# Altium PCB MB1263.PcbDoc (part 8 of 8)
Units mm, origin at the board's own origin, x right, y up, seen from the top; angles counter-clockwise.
Board outline 86 x 120 mm, 6 copper layers (Top Layer, Signal Layer 1, Signal Layer 2, Signal Layer 3, Signal Layer 4, Bottom Layer), stack 1.556 mm thick; 392 components, 421 nets, 1978 pads, 1444 vias.
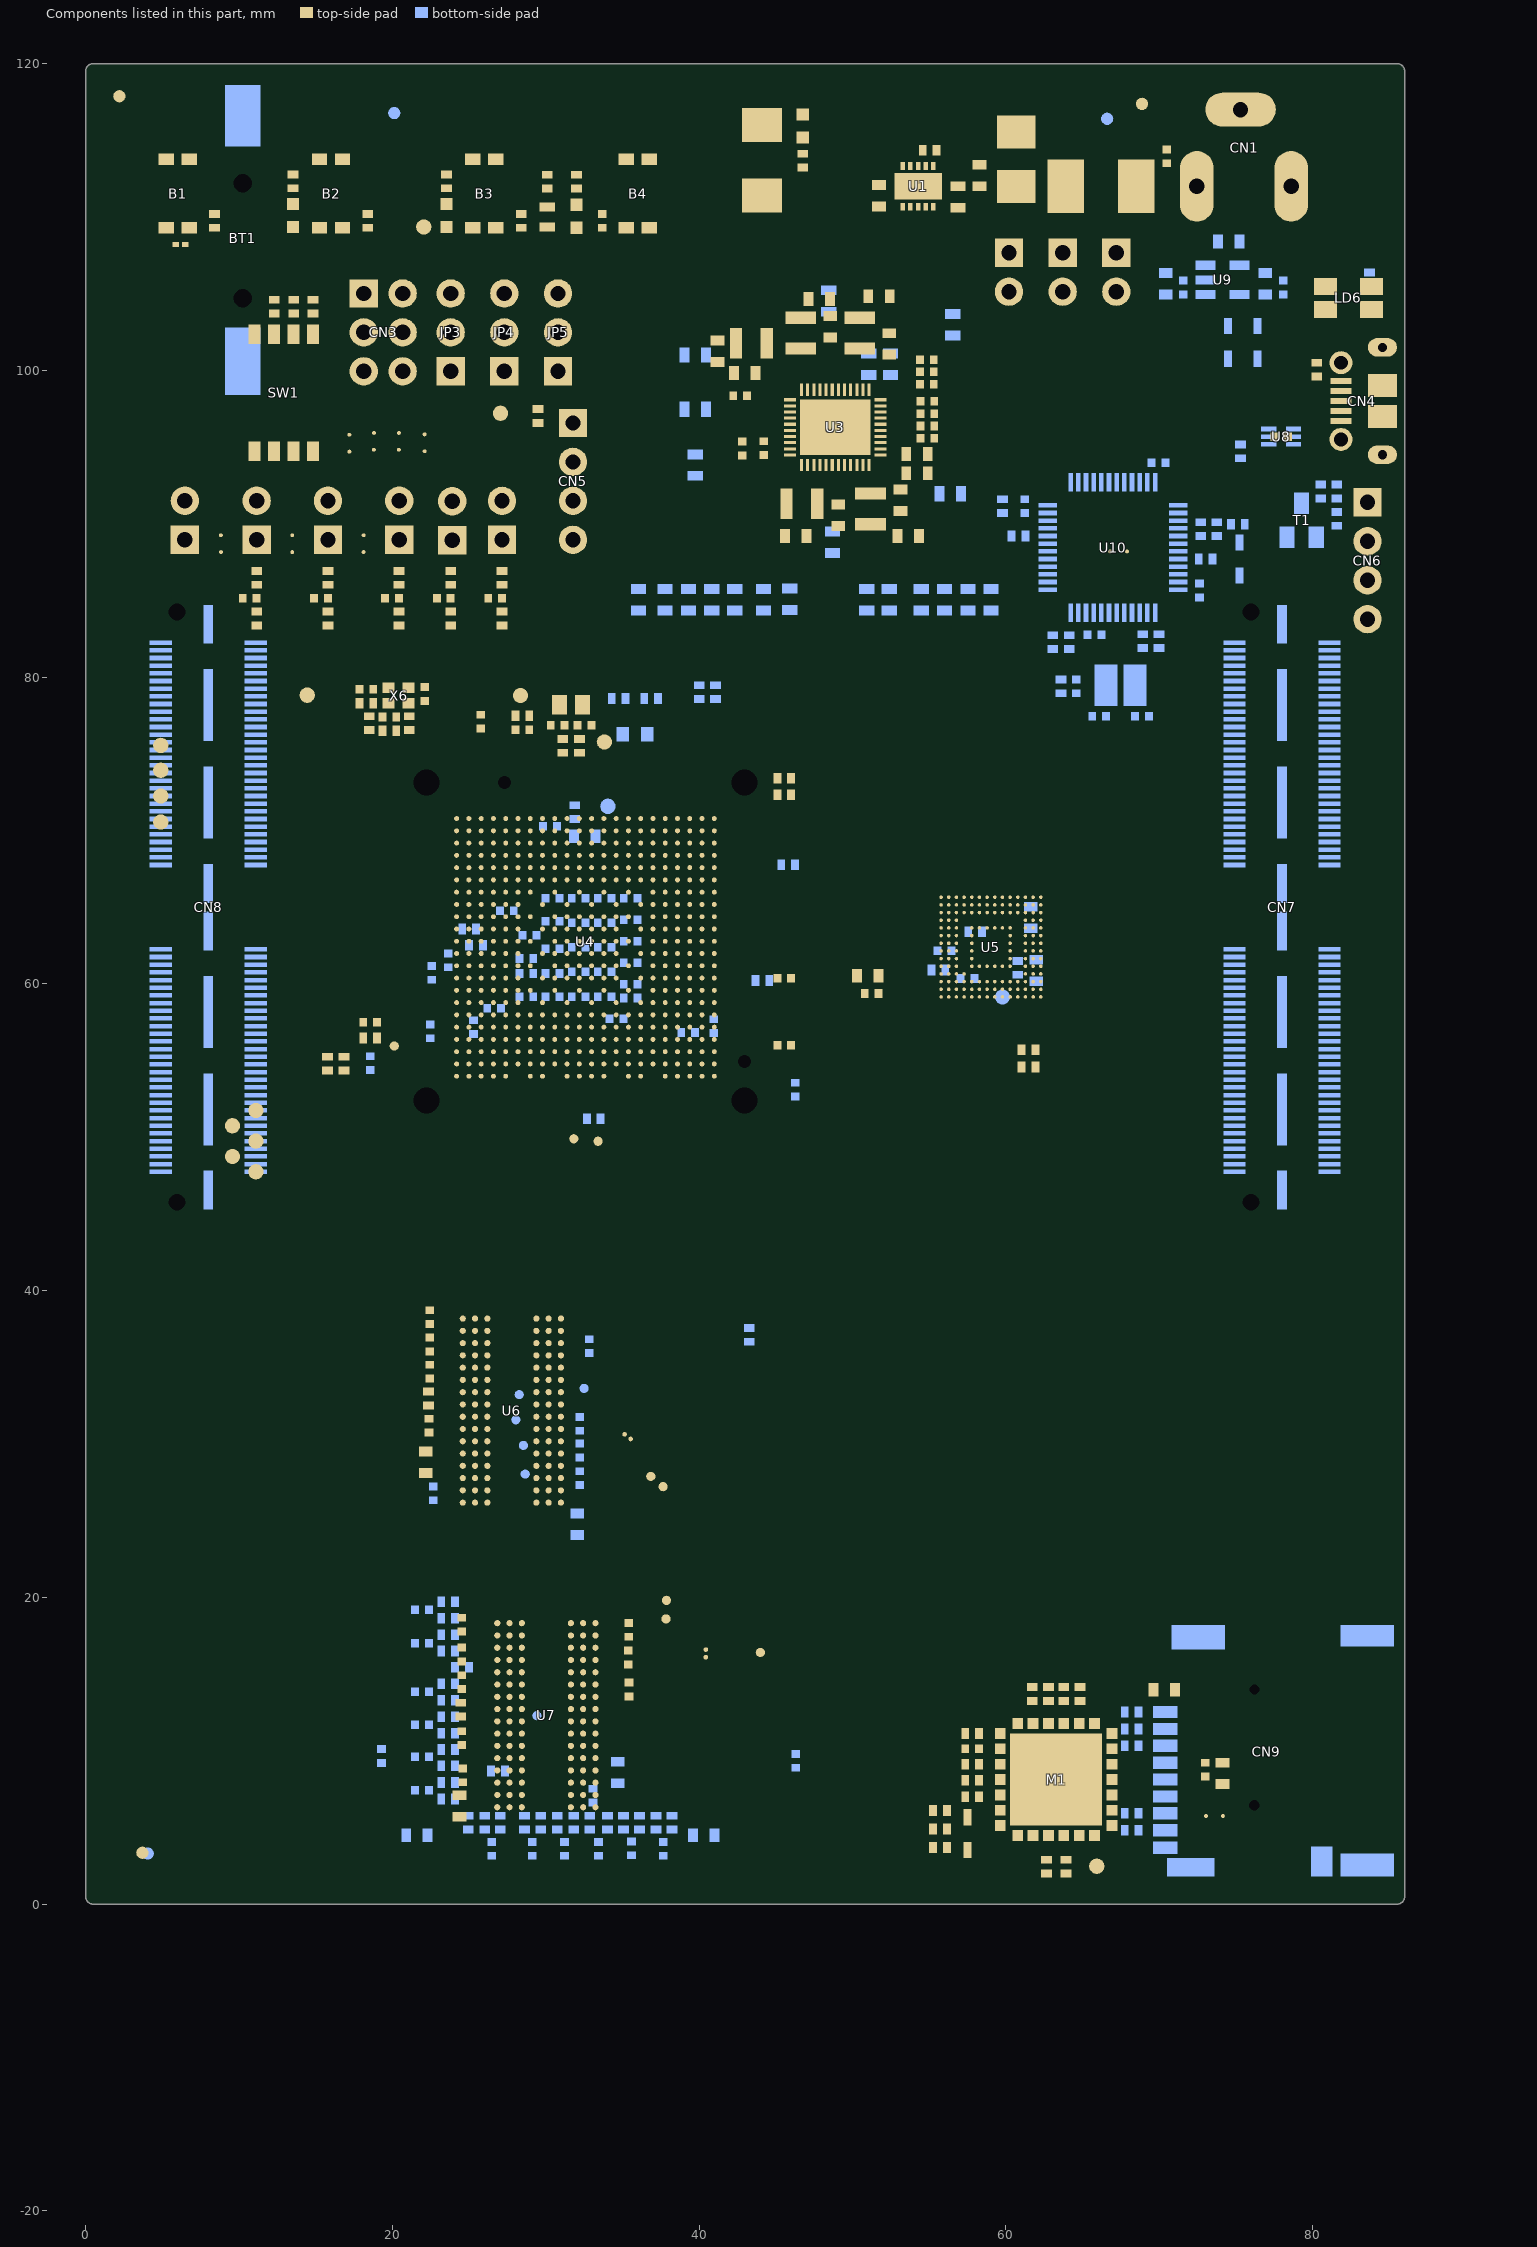
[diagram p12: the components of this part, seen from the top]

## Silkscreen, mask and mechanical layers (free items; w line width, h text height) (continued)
Drill Drawing:
  drawing of 518 lines, arcs and shapes, not listed
  text "IMPEDANCE TABLE" at -1,147.5 h3
  text "PCB SPECIFICATIONS :" at 94.25,146.25 h3
  text "LAYER" at 3.25,142.5 h3
  text "TRACE" at 19.5,142.5 h3
  text "SPACING" at 30,142.5 h3
  text "IMPEDANCE" at 43.5,142.5 h3
  text "IMPEDANCE" at 60.5,142.5 h3
  text "TOL." at 79.25,142.5 h3
  text "A.   MATERIAL :" at 94.25,142.25 h3
  text "FR-4" at 132.75,142.25 h3
  text "TG-170" at 149.25,142.25 h3
  text "X  TG-150" at 167.5,142.25 h3
  text "TG-140" at 183.5,142.25 h3
  text "(Single ended)" at 44,139.75 h2.5
  text "(Differentiel)" at 61.75,139.75 h2.5
  text "B.   MATERIAL FAMILY :" at 94.25,139.25 h3
  text "N/A" at 132.75,139.25 h3
  text "C.   SOLDERMASK COLOR :" at 94.25,136.25 h3
  text "GREEN" at 132.75,136.25 h3
  text "X  BLUE" at 149.25,136.25 h3
  text "RED" at 167.5,136.25 h3
  text "BLACK" at 183.5,136.25 h3
  text "TOP / BOTTOM" at -1,136 h3
  text "5.118" at 20.5,136 h3
  text "NA" at 32.5,136 h3
  text "50 ohm" at 47.25,136 h3
  text "NA" at 63.75,136 h3
  text "+/- 10%" at 77.75,136 h3
  text "D.   SILKSCREEN COLOR :" at 94.25,133.25 h3
  text "X  WHITE" at 132.75,133.25 h3
  text "YELLOW" at 149.25,133.25 h3
  text "BLACK" at 167.5,133.25 h3
  text "TOP / BOTTOM" at -1,132.5 h3
  text "4.72" at 20.5,132.5 h3
  text "NA" at 32.5,132.5 h3
  text "55 ohm" at 47.25,132.5 h3
  text "NA" at 63.75,132.5 h3
  text "+/- 10%" at 77.75,132.5 h3
  text "E.   SURFACE FINISH :" at 94.25,130.25 h3
  text "X  ENIG" at 132.75,130.25 h3
  text "IMMERSION SILVER" at 149.25,130.25 h3
  text "IMMERSION TIN" at 183.5,130.25 h3
  text "TOP / BOTTOM" at -1,129 h3
  text "3.937" at 20.5,129 h3
  text "5.118" at 32.5,129 h3
  text "NA" at 47.25,129 h3
  text "100 ohm" at 63.75,129 h3
  text "+/- 10%" at 77.75,129 h3
  text "HASL" at 132.75,127.25 h3
  text "HASL (PB-FREE)" at 149.25,127.25 h3
  text "GOLDEN FINGER" at 183.5,127.25 h3
  text "TOP / BOTTOM" at -1,125.5 h3
  text "3.937" at 20.5,125.5 h3
  text "3.543" at 32.5,125.5 h3
  text "NA" at 47.25,125.5 h3
  text "90 ohm" at 63.75,125.5 h3
  text "+/- 10%" at 77.75,125.5 h3
  text "F.   IMPEDANCE CONTROL :" at 94.25,124.25 h3
  text "NO" at 132.75,124.25 h3
  text "X  YES  (SEE IMPEDANCE TABLE FOR DETAIL INFORMATION)" at 149.25,124.25 h3
  text "G.   THROUGH VIA :" at 94.25,121.25 h3
  text "PLUG THE VIAS WHICH ARE COVERED WITH SOLDERMASK ONE OR TWO SIDE." at 132.75,121.25 h3
  text "PLUG MATERIAL :" at 132.75,118.25 h3
  text "X  SOLDERMASK" at 158.25,118.25 h3
  text "NON-CONDUCTIVE EPOXY." at 183.5,118.25 h3
  text "H.   STACK-UP :" at 94.25,115.25 h3
  text "SEE LAYER STACK-UP SEQUENCE FOR OVERALL THICKNESS." at 132.75,115.25 h3
  text "Layer" at 95.25,107.25 h2
  text "Name" at 103.624,107.25 h2
  text "Material" at 119.821,107.25 h2
  text "Thickness" at 134.375,107.25 h2
  text "Constant" at 146.33,107.25 h2
  text "Board Layer Stack" at 157.394,107.25 h2
  text "MINIMUN PARAMETERS" at 182.5,107 h3
  text "1" at 95.25,103.25 h2
  text "Top Overlay" at 103.624,103.25 h2
  text "DEFAULT" at 182.5,101.5 h3
  text "2" at 95.25,99.25 h2
  text "Top Solder" at 103.624,99.25 h2
  text "Solder Resist" at 119.821,99.25 h2
  text "0,80mil" at 134.375,99.25 h2
  text "3,5" at 146.33,99.25 h2
  text "TRACKS : 0.100mm           / GAPS : 0.100mm" at 182.5,95.75 h3
  text "3" at 95.25,95.25 h2
  text "Top Layer" at 103.624,95.25 h2
  text "Copper" at 119.821,95.25 h2
  text "1,46mil" at 134.375,95.25 h2
  text "4" at 95.25,91.25 h2
  text "Dielectric 1" at 103.624,91.25 h2
  text "FR-4" at 119.821,91.25 h2
  text "3,88mil" at 134.375,91.25 h2
  text "4,1" at 146.33,91.25 h2
  text "UNDER U3 (MPU)" at 182.5,89.25 h3
  text "5" at 95.25,87.25 h2
  text "Signal Layer 1" at 103.624,87.25 h2
  text "Copper" at 119.821,87.25 h2
  text "1,38mil" at 134.375,87.25 h2
  text "TRACKS : 0.090mm           / GAPS : 0.100mm" at 182.5,83.5 h3
  text "6" at 95.25,83.25 h2
  text "Dielectric 2" at 103.624,83.25 h2
  text "5,12mil" at 134.375,83.25 h2
  text "4,25" at 146.33,83.25 h2
  text "7" at 95.25,79.25 h2
  text "Signal Layer 2" at 103.624,79.25 h2
  text "Copper" at 119.821,79.25 h2
  text "1,38mil" at 134.375,79.25 h2
  text "UNDER U4 (EMMC)" at 182.5,77.25 h3
  text "8" at 95.25,75.25 h2
  text "Dielectric 3" at 103.624,75.25 h2
  text "34,84mil" at 134.375,75.25 h2
  text "4,25" at 146.33,75.25 h2
  text "TRACKS : 0.090mm           / GAPS : 0.090mm" at 182.5,71.5 h3
  text "9" at 95.25,71.25 h2
  text "Signal Layer 3" at 103.624,71.25 h2
  text "Copper" at 119.821,71.25 h2
  text "1,38mil" at 134.375,71.25 h2
  text "10" at 95.25,67.25 h2
  text "Dielectric 4" at 103.624,67.25 h2
  text "5,12mil" at 134.375,67.25 h2
  text "4,25" at 146.33,67.25 h2
  text "11" at 95.25,63.25 h2
  text "Signal Layer 4" at 103.624,63.25 h2
  text "Copper" at 119.821,63.25 h2
  text "1,38mil" at 134.375,63.25 h2
  text "12" at 95.25,59.25 h2
  text "Dielectric 5" at 103.624,59.25 h2
  text "3,88mil" at 134.375,59.25 h2
  text "4,1" at 146.33,59.25 h2
  text "13" at 95.25,55.25 h2
  text "Bottom Layer" at 103.624,55.25 h2
  text "Copper" at 119.821,55.25 h2
  text "1,46mil" at 134.375,55.25 h2
  text "14" at 95.25,51.25 h2
  text "Bottom Solder" at 103.624,51.25 h2
  text "Solder Resist" at 119.821,51.25 h2
  text "0,80mil" at 134.375,51.25 h2
  text "3,5" at 146.33,51.25 h2
  text "15" at 95.25,47.25 h2
  text "Bottom Overlay" at 103.624,47.25 h2
  text "Symbol" at 95.293,39.852 h2.4
  text "Count" at 104.692,39.852 h2.4
  text "Hole Size" at 115.323,39.852 h2.4
  text "Plated" at 133.6,39.852 h2.4
  text "Hole Type" at 141.851,39.852 h2.4
  text "Drill Layer Pair" at 153.863,39.852 h2.4
  text "Via/Pad" at 176.643,39.852 h2.4
  text "Hole Length" at 186.486,39.852 h2.4
  text "Routed Path Length" at 205.757,39.852 h2.4
  text "1" at 104.692,35.709 h2
  text "0,650mm (25,59mil)" at 115.323,35.709 h2
  text "NPTH" at 133.6,35.709 h2
  text "Round" at 141.851,35.709 h2
  text "Top Layer - Bottom Layer" at 153.863,35.709 h2
  text "Pad" at 176.643,35.709 h2
  text "-" at 186.486,35.709 h2
  text "-" at 205.757,35.709 h2
  text "1" at 104.692,31.565 h2
  text "0,700mm (27,56mil)" at 115.323,31.565 h2
  text "NPTH" at 133.6,31.565 h2
  text "Round" at 141.851,31.565 h2
  text "Top Layer - Bottom Layer" at 153.863,31.565 h2
  text "Pad" at 176.643,31.565 h2
  text "-" at 186.486,31.565 h2
  text "-" at 205.757,31.565 h2
  text "2" at 104.692,27.422 h2
  text "0,600mm (23,62mil)" at 115.323,27.422 h2
  text "PTH" at 133.6,27.422 h2
  text "Slot" at 141.851,27.422 h2
  text "Top Layer - Bottom Layer" at 153.863,27.422 h2
  text "Pad" at 176.643,27.422 h2
  text "1,300mm (51,18mil)" at 186.486,27.422 h2
  text "0,700mm (27,56mil)" at 205.757,27.422 h2
  text "2" at 104.692,23.279 h2
  text "0,850mm (33,47mil)" at 115.323,23.279 h2
  text "NPTH" at 133.6,23.279 h2
  text "Round" at 141.851,23.279 h2
  text "Top Layer - Bottom Layer" at 153.863,23.279 h2
  text "Pad" at 176.643,23.279 h2
  text "-" at 186.486,23.279 h2
  text "-" at 205.757,23.279 h2
  text "2" at 104.692,19.136 h2
  text "0,900mm (35,43mil)" at 115.323,19.136 h2
  text "PTH" at 133.6,19.136 h2
  text "Round" at 141.851,19.136 h2
  text "Top Layer - Bottom Layer" at 153.863,19.136 h2
  text "Pad" at 176.643,19.136 h2
  text "-" at 186.486,19.136 h2
  text "-" at 205.757,19.136 h2
  text "2" at 104.692,14.993 h2
  text "1,200mm (47,24mil)" at 115.323,14.993 h2
  text "NPTH" at 133.6,14.993 h2
  text "Round" at 141.851,14.993 h2
  text "Top Layer - Bottom Layer" at 153.863,14.993 h2
  text "Pad" at 176.643,14.993 h2
  text "-" at 186.486,14.993 h2
  text "-" at 205.757,14.993 h2
  text "3" at 104.692,10.85 h2
  text "1,000mm (39,37mil)" at 115.323,10.85 h2
  text "PTH" at 133.6,10.85 h2
  text "Slot" at 141.851,10.85 h2
  text "Top Layer - Bottom Layer" at 153.863,10.85 h2
  text "Pad" at 176.643,10.85 h2
  text "3,500mm (137,80mil)" at 186.486,10.85 h2
  text "2,500mm (98,43mil)" at 205.757,10.85 h2
  text "4" at 104.692,6.707 h2
  text "1,100mm (43,31mil)" at 115.323,6.707 h2
  text "NPTH" at 133.6,6.707 h2
  text "Round" at 141.851,6.707 h2
  text "Top Layer - Bottom Layer" at 153.863,6.707 h2
  text "Pad" at 176.643,6.707 h2
  text "-" at 186.486,6.707 h2
  text "-" at 205.757,6.707 h2
  text "4" at 104.692,2.564 h2
  text "1,700mm (66,93mil)" at 115.323,2.564 h2
  text "NPTH" at 133.6,2.564 h2
  text "Round" at 141.851,2.564 h2
  text "Top Layer - Bottom Layer" at 153.863,2.564 h2
  text "Pad" at 176.643,2.564 h2
  text "-" at 186.486,2.564 h2
  text "-" at 205.757,2.564 h2
  text "41" at 104.692,-1.579 h2
  text "1,000mm (39,37mil)" at 115.323,-1.579 h2
  text "PTH" at 133.6,-1.579 h2
  text "Round" at 141.851,-1.579 h2
  text "Top Layer - Bottom Layer" at 153.863,-1.579 h2
  text "Pad" at 176.643,-1.579 h2
  text "-" at 186.486,-1.579 h2
  text "-" at 205.757,-1.579 h2
  text "670" at 104.692,-5.722 h2
  text "0,300mm (11,81mil)" at 115.323,-5.722 h2
  text "PTH" at 133.6,-5.722 h2
  text "Round" at 141.851,-5.722 h2
  text "Top Layer - Bottom Layer" at 153.863,-5.722 h2
  text "Via" at 176.643,-5.722 h2
  text "-" at 186.486,-5.722 h2
  text "-" at 205.757,-5.722 h2
  text "774" at 104.692,-9.865 h2
  text "0,200mm (7,87mil)" at 115.323,-9.865 h2
  text "PTH" at 133.6,-9.865 h2
  text "Round" at 141.851,-9.865 h2
  text "Top Layer - Bottom Layer" at 153.863,-9.865 h2
  text "Via" at 176.643,-9.865 h2
  text "-" at 186.486,-9.865 h2
  text "-" at 205.757,-9.865 h2
  text ".Layer_Name" at 7.068,-11.667 h3
  text ".DRL" at 48.763,-11.667 h3
  text "1506 Total" at 104.692,-14.009 h2
  text "Slot definitions :" at 95.293,-16.909 h2
  text "Routed Path Length" at 108.946,-16.909 h2
  text "= Calculated from tool start centre position to tool end centre position." at 125.859,-16.909 h2
  text "Hole Length" at 108.946,-18.566 h2
  text "= Routed Path Length + Tool Size = Slot length as defined in the PCB layout" at 119.58,-18.566 h2
M20-Top Sheet Box:
  circle w0.254: c85.072,-18.388 r1.3
  region: 84.598,-11.151 69.07,-11.151 68.376,-12.927 67.165,-14.152 65.768,-12.292 65.768,-10.641 66.911,-9.244 68.347,-8.865 84.598,-8.865
  region: 70.594,-19.481 59.838,-19.481 60.832,-16.988 68.689,-16.988 69.138,-16.229 71.347,-18.777
  lines w0.254: 60.832,-16.988 69.624,-16.988 66.557,-13.45 cw(c68.361,-11.506) 68.601,-8.865 85.365,-8.865 84.603,-11.151 ; 64.145,-8.618 cw(c66.572,-9.589) 66.808,-6.986 ; 64.185,-8.586 59.838,-19.481 79.161,-19.481 ccw(c79.41,-16.746) 81.959,-17.766 ; 65.924,-12.52 71.347,-18.777 ; 66.178,-12.52 71.483,-18.642 ; 66.178,-12.266 71.483,-18.388 ; 66.276,-11.151 79.269,-11.151 ; 66.305,-12.139 71.61,-18.261 ; 66.432,-12.012 71.737,-18.134 ; 66.559,-11.885 71.864,-18.007 ; 66.686,-11.758 71.991,-17.88 ; 66.741,-9.806 72.046,-15.927 ; 66.809,-6.986 86.259,-6.986 81.96,-17.764 ; 66.813,-11.631 72.064,-17.69 ; 66.813,-11.377 72.118,-17.499 ; 66.813,-11.123 72.118,-17.245 ; 66.813,-10.234 72.118,-16.356 ; 66.94,-10.996 72.245,-17.118 ; 66.94,-10.615 72.245,-16.737 ; 68.312,-17.001 ccw(c68.417,-16.466) 68.715,-16.009 ; 69.399,-11.138 ccw(c69.373,-11.705) 69.042,-12.167 71.407,-14.896 cw(c69.603,-16.84) 70.336,-19.389 ; 75.68,-19.277 78.569,-10.897 ; 75.902,-19.227 78.771,-10.906 ; 76.029,-19.227 78.898,-10.906 ; 76.283,-19.227 79.152,-10.906 ; 76.537,-19.227 79.406,-10.906 ; 76.791,-19.227 79.66,-10.906 ; 77.045,-19.227 79.914,-10.906 ; 77.299,-19.227 80.168,-10.906 ; 77.553,-19.227 80.422,-10.906 ; 77.807,-19.227 80.676,-10.906 ; 78.016,-19.277 80.905,-10.897 ; 80.905,-11.151 84.598,-11.151 ; 83.929,-11.149 84.691,-8.863 ; 84.095,-11.151 84.857,-8.865 ; 84.349,-11.151 85.111,-8.865
  lines w0.3: -1.932,-23.367 88.068,-23.367 88.068,-3.367 -1.932,-3.367 ; -1.932,-18.367 58.068,-18.367 ; -1.932,-13.367 58.068,-13.367 ; -1.932,-8.367 58.068,-8.367 ; -1.932,-23.367 -1.932,-3.367 ; 38.068,-23.367 38.068,-8.367 ; 58.068,-23.367 58.068,-3.367 ; 75.68,-19.277 78.016,-19.277
  text "Project: '.Board_Name'" at -0.932,-6.583 h3
  text "Layer:" at -0.932,-11.667 h3
  text "Gerber:" at 39.057,-11.667 h3
  text "Variant: '.VariantName'" at -0.932,-16.667 h3
  text "Ref: MB1263" at 39.184,-16.667 h3
  text "R" at 84.564,-19.15 h1.52
  text "Date: 18-OCTOBER-08" at -0.932,-21.667 h3
  text "Rev: '.Board_PCB_Revision'" at 39.127,-21.667 h3
M21-Bottom Sheet Box:
  circle w0.254: c1.251,-18.388 r1.3
  region: 15.729,-19.481 26.485,-19.481 25.492,-16.988 17.634,-16.988 17.185,-16.229 14.977,-18.777
  region: 1.726,-11.151 17.253,-11.151 17.947,-12.927 19.158,-14.152 20.555,-12.292 20.555,-10.641 19.412,-9.244 17.976,-8.865 1.726,-8.865
  lines w0.254: 1.212,-8.865 1.974,-11.151 ; 1.466,-8.865 2.228,-11.151 ; 1.632,-8.863 2.394,-11.149 ; 1.72,-11.151 0.958,-8.865 17.722,-8.865 cw(c17.962,-11.506) 19.766,-13.45 16.7,-16.988 25.492,-16.988 ; 1.726,-11.151 5.418,-11.151 ; 4.363,-17.764 0.064,-6.986 19.514,-6.986 ; 4.364,-17.766 ccw(c6.914,-16.746) 7.162,-19.481 26.485,-19.481 22.139,-8.586 ; 5.418,-10.897 8.307,-19.277 ; 5.647,-10.906 8.516,-19.227 ; 5.901,-10.906 8.77,-19.227 ; 6.155,-10.906 9.024,-19.227 ; 6.409,-10.906 9.278,-19.227 ; 6.663,-10.906 9.532,-19.227 ; 6.917,-10.906 9.786,-19.227 ; 7.054,-11.151 20.047,-11.151 ; 7.171,-10.906 10.04,-19.227 ; 7.425,-10.906 10.294,-19.227 ; 7.552,-10.906 10.421,-19.227 ; 7.754,-10.897 10.643,-19.277 ; 14.078,-17.118 19.383,-10.996 ; 14.078,-16.737 19.383,-10.615 ; 14.205,-17.499 19.51,-11.377 ; 14.205,-17.245 19.51,-11.123 ; 14.205,-16.356 19.51,-10.234 ; 14.259,-17.69 19.51,-11.631 ; 14.277,-15.927 19.582,-9.806 ; 14.332,-17.88 19.637,-11.758 ; 14.459,-18.007 19.764,-11.885 ; 14.586,-18.134 19.891,-12.012 ; 14.713,-18.261 20.018,-12.139 ; 14.84,-18.642 20.145,-12.52 ; 14.84,-18.388 20.145,-12.266 ; 14.977,-18.777 20.399,-12.52 ; 15.987,-19.389 cw(c16.72,-16.84) 14.916,-14.896 17.281,-12.167 ccw(c16.951,-11.705) 16.925,-11.138 ; 17.608,-16.009 ccw(c17.906,-16.466) 18.011,-17.001 ; 19.515,-6.986 cw(c19.752,-9.589) 22.178,-8.618
  lines w0.3: 8.307,-19.277 10.643,-19.277 ; 28.068,-23.367 28.068,-3.367 ; 28.068,-18.367 88.068,-18.367 ; 28.068,-13.367 88.068,-13.367 ; 28.068,-8.367 88.068,-8.367 ; 48.068,-23.367 48.068,-8.367 ; -1.932,-23.367 88.068,-23.367 88.068,-3.367 -1.932,-3.367 -1.932,-23.367
  text "Project: '.Board_Name'" at 86.874,-6.583 h3
  text "Gerber:" at 46.885,-11.667 h3
  text "Layer:" at 86.874,-11.667 h3
  text "Ref: MB1263" at 46.885,-16.667 h3
  text "Variant: '.VariantName'" at 86.874,-16.667 h3
  text "R" at 1.759,-19.15 h1.52
  text "Rev: '.Board_PCB_Revision'" at 46.942,-21.667 h3
  text "Date: 18-OCTOBER-08" at 86.874,-21.667 h3

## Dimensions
0,119.5 to 0,0.5 on M2-Board Dimensions
0,119.5 to 0.5,120 on M2-Board Dimensions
